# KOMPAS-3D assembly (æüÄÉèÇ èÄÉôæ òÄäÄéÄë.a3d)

Referenced files in D:\МОДЕЛЬ ТАНКА Т90\СБОРКИ\СБОРКА КОРПУСА ШТАМПОВКА\: СБОРКА КОРПУС.a3d
Referenced files in D:\МОДЕЛЬ ТАНКА Т90\ДЕТАЛИ\ХОДОВАЯ\Ленивец с эксцентриком\: ось эксцентрика ленивца.m3d
Referenced files in D:\МОДЕЛЬ ТАНКА Т90\СБОРКИ\СБОРКА ХОДОВАЯ\: Сборка ленивец с эксцентриком.a3d, Сборка каток поддерживающий.a3d, Сборка звездочка с осями.a3d, Сборка каток с балансиром полностью.a3d, Сборка гусеница30.a3d, Сборка трак мелкий.a3d, Сборка гусеница5.a3d, Сборка гусеница15.a3d
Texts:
  СБОРКА КОРУС ХОДОВОЙ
